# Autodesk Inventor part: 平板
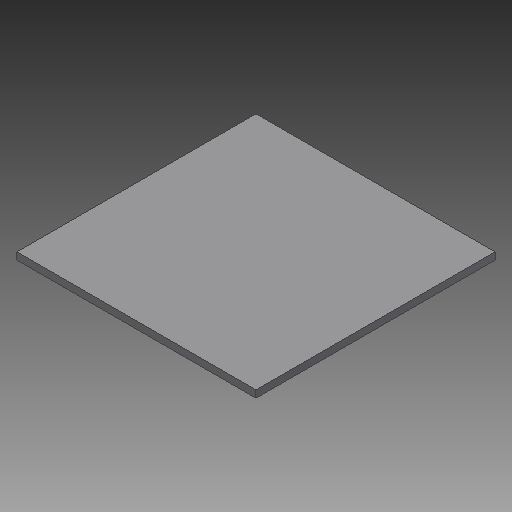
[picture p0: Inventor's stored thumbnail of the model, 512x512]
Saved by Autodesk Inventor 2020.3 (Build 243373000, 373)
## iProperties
RuleStatus: InUse
BeforeDocSave0: 重量提取
Part Number: 平板
Material: Q235B
Description: Metal
Document SubType Name: 钣金
Mass: 235.5 g
Surface Area: 212 cm^2
Volume: 30 cm^3
Density: 7.85 g/cm^3
Sheet Metal Rule: 默认_mm
Appearance: Q235B
重量: 0.24
文件类型: 钣金件
规格材料: t3/Q235B
Author: 陈驹祥
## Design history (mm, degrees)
node "平板1"
  sketch "草图3"
    geometry: L1 (-50, 50)-(50, 50); L2 (50, 50)-(50, -50); L3 (50, -50)-(-50, -50); L4 (-50, -50)-(-50, 50); L5 (-50, 50)-(50, -50); L6 (50, 50)-(-50, -50); 1 further point
    constraints: 12 end point, 2 midpoint, 2 parallel, 1 horizontal, 1 perpendicular
    dimensions: "LA" = 100 distance of L1.end L2.end; "LB" = 100 distance of L2.end L3.end
node "实体3"
other parameters: "厚度" = 3, "K系数" = 4.4, "折弯半径" = 3 (= 厚度), "折弯释压宽度" = 3 (= 厚度), "折弯释压深度" = 1.5 (= 0.5 x 厚度), "拐角释压尺寸" = 12 (= 4 x 厚度), "焊缝间隙" = 0.01, "最小余量" = 6 (= 2 x 厚度), "过渡半径" = 3 (= 折弯半径), "Jacobi半径尺寸" = 3 (= 折弯半径), "间隙大小" = 3 (= 厚度), "d6" = 3 (= 厚度)
